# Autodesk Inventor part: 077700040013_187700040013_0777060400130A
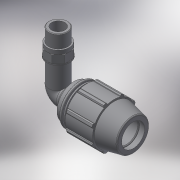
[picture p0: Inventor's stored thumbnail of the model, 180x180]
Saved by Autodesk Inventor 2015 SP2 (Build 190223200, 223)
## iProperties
Created: 2017-02
Part Number: 077700040013_187700040013_0777060400130A
Material: Generic
Description: PLASSON 90° ELBOW MALE WITH INTEGRAL BRASS THREAD 40-1.1/4"
Document SubType Name: Modeling
Designer: KIM
Mass: 174.249 g
Surface Area: 431.906 cm^2
Volume: 174.249 cm^3
Density: 1 g/cm^3
Appearance: Default
Author: KIM
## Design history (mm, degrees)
derived "07770.ipt"
feature "Solid1::07770.ipt"
tag "TaggingFeature1"
body "Solid1"
other parameters: "d4" = 10.33333, "d5" = 31, "d7" = 82, "d9" = 17.71429, "d11" = 4.13333, "d13" = 120 deg, "d14" = 56, "d15" = 12 deg, "d16" = 71.34, "d18" = 2, "d19" = 35 deg, "d20" = 17.5 deg, "d21" = 76.26, "d23" = 0, "d25" = 360 deg, "d27" = 1.64, "d33" = 0.8, "d42" = 45.88, "d43" = 2.46, "d46" = 1.2, "d51" = 124, "d68" = 8.26667, "d73" = 41.91, "d74" = 22, "d75" = 48.1965, "d76" = 29.337, "d79" = 16.764, "d80" = 1.2573, "d83" = 0, "d84" = 0, "d91" = 61.5, "d93" = 84, "d94" = 41.91, "d95" = 29.337, "d96" = 8.26667, "d97" = 50 deg, "d98" = 2.06667, "d99" = 69.1998, "d100" = 2.06667, "d101" = 2.06667, "d105" = 2.2, "d106" = 50.292, "d107" = 22, "d108" = 13.2, "d109" = 0, "E_" = 82, "A_" = 124, "l_" = 84, "l_2" = 22, "R_" = 41.91
